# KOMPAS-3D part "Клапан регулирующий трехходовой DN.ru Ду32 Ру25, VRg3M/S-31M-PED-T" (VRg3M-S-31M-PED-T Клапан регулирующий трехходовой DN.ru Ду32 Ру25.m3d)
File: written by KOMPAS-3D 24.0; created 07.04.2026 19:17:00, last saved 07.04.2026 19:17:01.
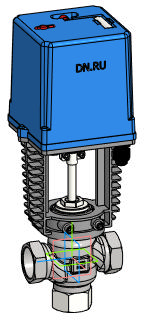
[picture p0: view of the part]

Document properties: Автор: DN.RU; Полное имя файла: D:\PROJECT CAD\DN.RU\...197(ACTUALE). VRg3M-S-31M-PED-T Клапан регулирующий трехходовой DN.ru\Исходники\DN32\VRg3M-S-31M-PED-T Клапан регулирующий трехходовой DN.ru Ду32 Ру25.m3d

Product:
- Body: Твердое тело1  | qty 1
    Масса: 20.152813
- Part/product: Клапан регулирующий трехходовой DN.ru Ду32 Ру25  | designation VRg3M/S-31M-PED-T
    Масса: 3.7
    Раздел спецификации: Прочие изделия
    Комментарий: D230-11266
    Примечание: D230-11266
    additional columns: Типовые

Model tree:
1. Твердое тело1  (labels: Твердое тело1)

Expressions: VRg3M/S-31M-PED-T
